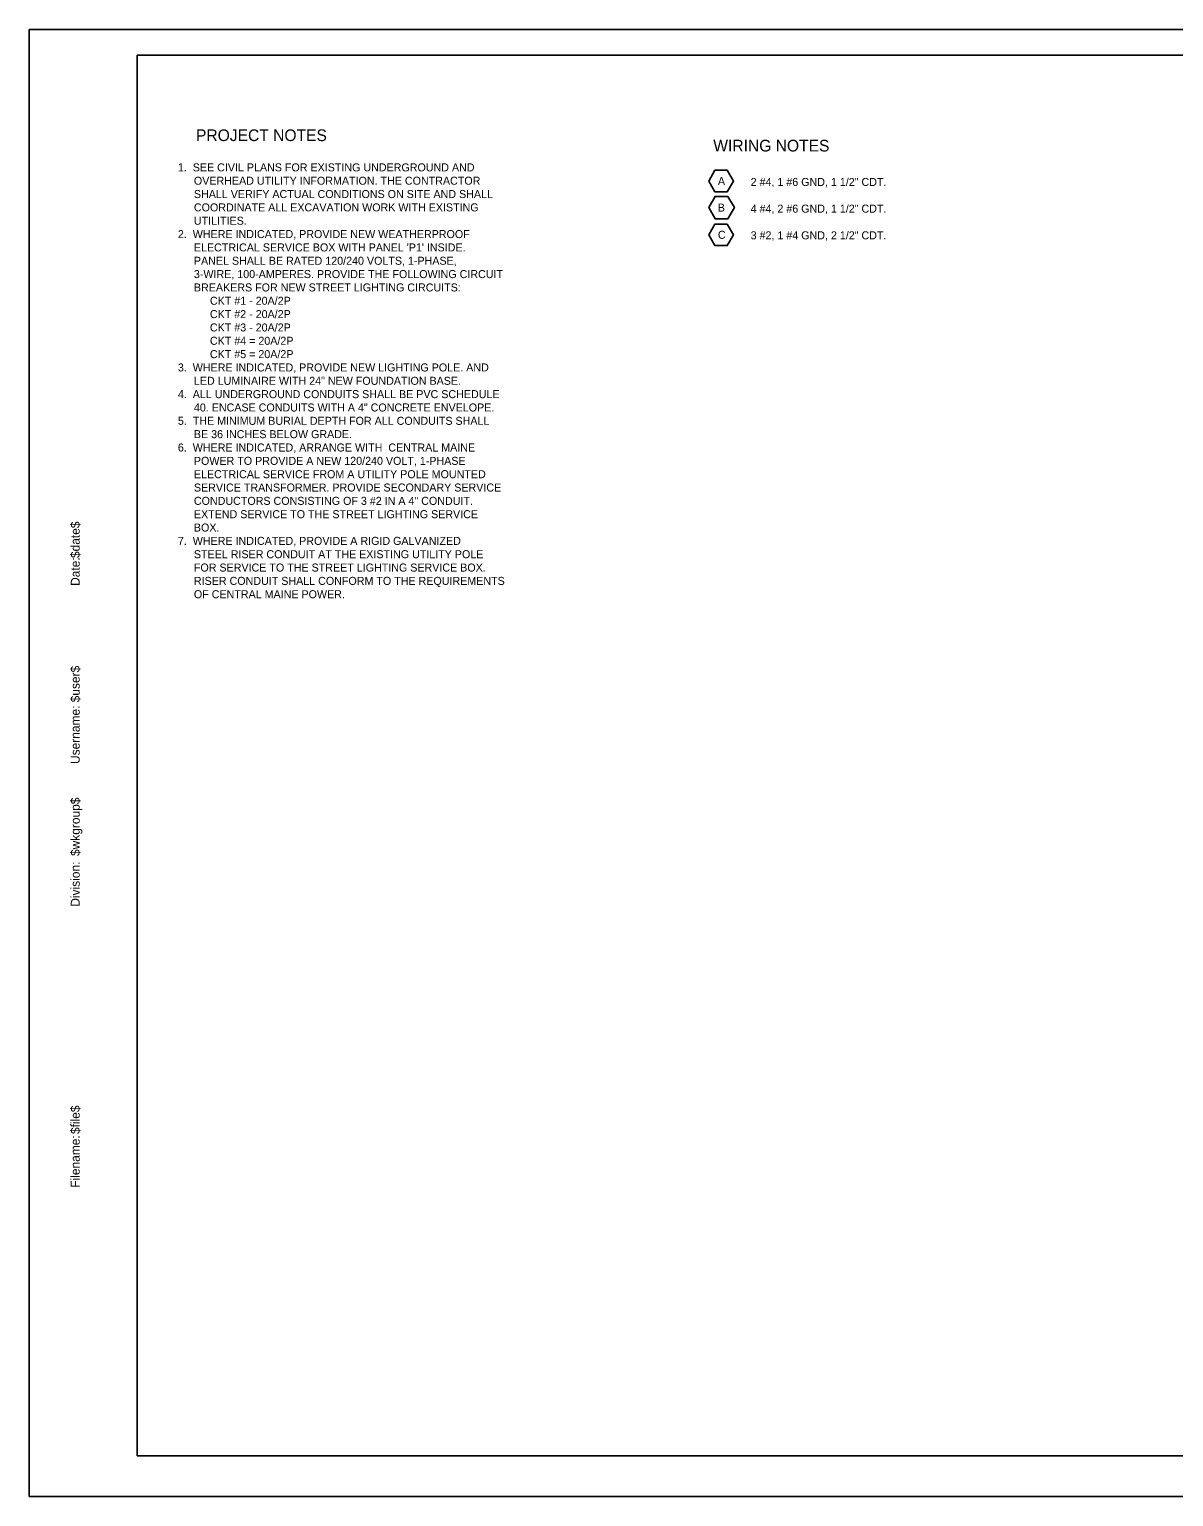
# Model space of a CAD drawing. Extents: x 9916 to 916479, y 6678 to 329942.
# Drawn here: x 915621 to 916050, y 329392 to 329942 of the extents above; entities that cross this region are included whole.
import ezdxf

# ---------------------------------------------------------------- set-up
doc = ezdxf.new("R2010")
doc.units = 0
for name, color, linetype in [('ANNOTATION', 7, 'Continuous'), ('Border', 7, 'Continuous'), ('PLOT BOUNDARY', 7, 'Continuous')]:
    doc.layers.add(name, color=color, linetype=linetype)

msp = doc.modelspace()

# ---------------------------------------------------------------- linework, layer by layer
at = {"layer": 'ANNOTATION'}
for points in [[(915882.9, 329888.88), (915878.24, 329888.88), (915875.91, 329884.84), (915878.24, 329880.8), (915882.9, 329880.8), (915885.24, 329884.84)], [(915883.14, 329879.06), (915878.32, 329879.06), (915875.91, 329874.88), (915878.32, 329870.7), (915883.14, 329870.7), (915885.55, 329874.88)], [(915882.9, 329868.72), (915878.24, 329868.72), (915875.91, 329864.69), (915878.24, 329860.65), (915882.9, 329860.65), (915885.24, 329864.69)]]:
    msp.add_lwpolyline(points, close=True, dxfattribs=at)
at = {"layer": 'Border'}
for p, q in [((916461.64, 329932), (915661.64, 329932)), ((915661.64, 329932), (915661.64, 329407)), ((915661.64, 329407), (916461.64, 329407))]:
    msp.add_line(p, q, dxfattribs=at)
at = {"layer": 'PLOT BOUNDARY'}
msp.add_lwpolyline([(915621.17, 329391.7), (916471.17, 329391.7), (916471.17, 329941.7), (915621.17, 329941.7)], close=True, dxfattribs=at)

# ---------------------------------------------------------------- texts
at = {"layer": 'ANNOTATION'}
for s, height, p in [('PROJECT NOTES', 4.375, (915683.67, 329899.82)), ('WIRING NOTES', 4.375, (915877.64, 329895.92)), ('1.  SEE CIVIL PLANS FOR EXISTING UNDERGROUND AND ', 3, (915676.88, 329888.46)), ('OVERHEAD UTILITY INFORMATION. THE CONTRACTOR ', 3, (915682.88, 329883.46)), ('A', 3, (915879.37, 329883.34)), ('2 #4, 1 #6 GND, 1 1/2" CDT.', 3, (915891.65, 329882.99)), ('SHALL VERIFY ACTUAL CONDITIONS ON SITE AND SHALL ', 3, (915682.88, 329878.46)), ('COORDINATE ALL EXCAVATION WORK WITH EXISTING ', 3, (915682.88, 329873.46)), ('B', 3, (915879.32, 329873.38)), ('4 #4, 2 #6 GND, 1 1/2" CDT.', 3, (915891.65, 329872.99)), ('UTILITIES.', 3, (915682.88, 329868.46)), ('2.  WHERE INDICATED, PROVIDE NEW WEATHERPROOF ', 3, (915676.88, 329863.46)), ('C', 3, (915879.37, 329863.19)), ('3 #2, 1 #4 GND, 2 1/2" CDT.', 3, (915891.65, 329862.99)), ("ELECTRICAL SERVICE BOX WITH PANEL 'P1' INSIDE. ", 3, (915682.88, 329858.46)), ('PANEL SHALL BE RATED 120/240 VOLTS, 1-PHASE, ', 3, (915682.88, 329853.46)), ('3-WIRE, 100-AMPERES. PROVIDE THE FOLLOWING CIRCUIT ', 3, (915682.88, 329848.46)), ('BREAKERS FOR NEW STREET LIGHTING CIRCUITS:', 3, (915682.88, 329843.46)), ('CKT #1 - 20A/2P', 3, (915688.88, 329838.46)), ('CKT #2 - 20A/2P', 3, (915688.88, 329833.46)), ('CKT #3 - 20A/2P', 3, (915688.88, 329828.46)), ('CKT #4 = 20A/2P', 3, (915688.88, 329823.46)), ('CKT #5 = 20A/2P', 3, (915688.88, 329818.46)), ('3.  WHERE INDICATED, PROVIDE NEW LIGHTING POLE. AND ', 3, (915676.88, 329813.46)), ('LED LUMINAIRE WITH 24" NEW FOUNDATION BASE.', 3, (915682.88, 329808.46)), ('4.  ALL UNDERGROUND CONDUITS SHALL BE PVC SCHEDULE ', 3, (915676.88, 329803.46)), ('40. ENCASE CONDUITS WITH A 4" CONCRETE ENVELOPE.', 3, (915682.88, 329798.46)), ('5.  THE MINIMUM BURIAL DEPTH FOR ALL CONDUITS SHALL ', 3, (915676.88, 329793.46)), ('BE 36 INCHES BELOW GRADE.', 3, (915682.88, 329788.46)), ('6.  WHERE INDICATED, ARRANGE WITH  CENTRAL MAINE ', 3, (915676.88, 329783.46)), ('POWER TO PROVIDE A NEW 120/240 VOLT, 1-PHASE ', 3, (915682.88, 329778.46)), ('ELECTRICAL SERVICE FROM A UTILITY POLE MOUNTED ', 3, (915682.88, 329773.46)), ('SERVICE TRANSFORMER. PROVIDE SECONDARY SERVICE ', 3, (915682.88, 329768.46)), ('CONDUCTORS CONSISTING OF 3 #2 IN A 4" CONDUIT. ', 3, (915682.88, 329763.46)), ('EXTEND SERVICE TO THE STREET LIGHTING SERVICE ', 3, (915682.88, 329758.46)), ('BOX.', 3, (915682.88, 329753.46)), ('7.  WHERE INDICATED, PROVIDE A RIGID GALVANIZED ', 3, (915676.88, 329748.46)), ('STEEL RISER CONDUIT AT THE EXISTING UTILITY POLE ', 3, (915682.88, 329743.46)), ('FOR SERVICE TO THE STREET LIGHTING SERVICE BOX. ', 3, (915682.88, 329738.46)), ('RISER CONDUIT SHALL CONFORM TO THE REQUIREMENTS ', 3, (915682.88, 329733.46)), ('OF CENTRAL MAINE POWER.', 3, (915682.88, 329728.46))]:
    msp.add_text(s, height=height, dxfattribs=at).set_placement(p)
at = {"layer": 'Border'}
for s, p in [('$date$', (915640.06, 329743.52)), ('Date:', (915640.06, 329733.08)), ('$user$', (915640.06, 329689.45)), ('Username:', (915640.06, 329666.33)), ('$wkgroup$', (915640.06, 329631.84)), ('Division:', (915640.06, 329612.83)), ('$file$', (915640.06, 329527.62)), ('Filename:', (915640.06, 329507.49))]:
    msp.add_text(s, height=3.348, rotation=90, dxfattribs=at).set_placement(p)

doc.saveas('drawing.dxf')
